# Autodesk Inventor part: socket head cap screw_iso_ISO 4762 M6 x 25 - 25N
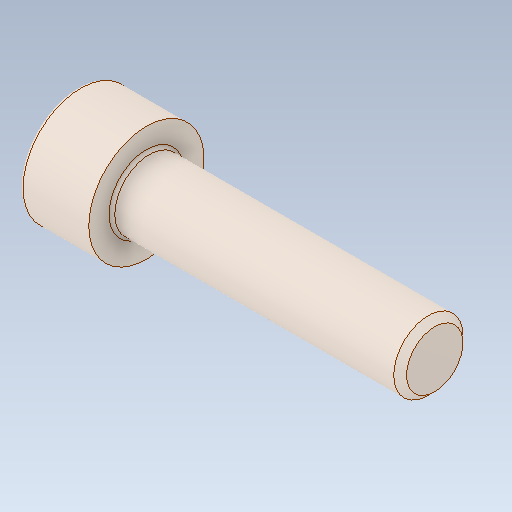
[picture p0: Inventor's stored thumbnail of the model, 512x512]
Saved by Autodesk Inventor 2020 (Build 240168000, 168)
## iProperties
Created: 1999-08
Part Number: socket head cap screw_iso_ISO 4762 M6 x 25 - 25N
Material: Ogólny
Document SubType Name: Modeling
Designer: Tomasz
Density: 1 g/cm^3
Appearance: Domyślna
Sending System: SolidWorks 2017
Last Author: Tomasz
Last Saved: 2017-11-19
Author: Tomasz
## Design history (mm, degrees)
feature "Hex"
node "Bryła1"
